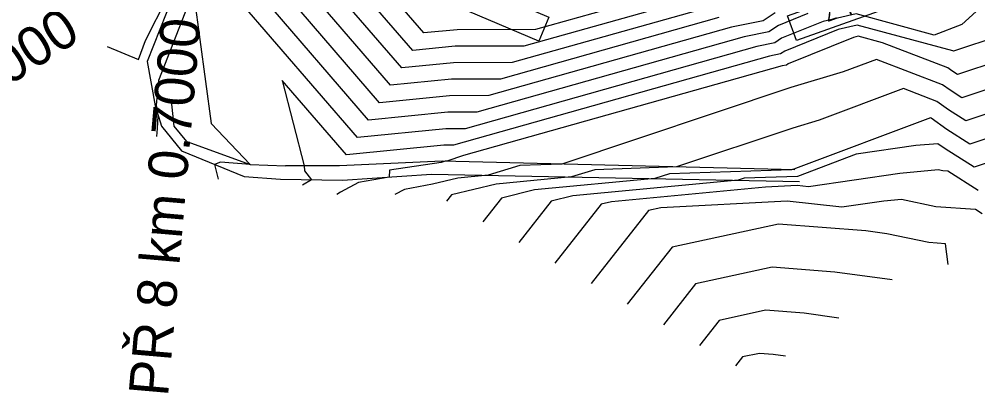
# Model space of a CAD drawing. Extents: x -549394 to -546608, y -1037055 to -1033629.
# Drawn here: x -548286 to -548066.1, y -1035761.5 to -1035675.8 of the extents above; entities that cross this region are included whole.
import ezdxf

# ---------------------------------------------------------------- set-up
doc = ezdxf.new("R2010")
doc.units = 0
for name, color, linetype in [('hlavni_vrst', 7, 'Continuous'), ('hrana_L', 7, 'Continuous'), ('norm_vrst', 7, 'Continuous'), ('x_popis_oblouky_C11', 7, 'Continuous'), ('x_popis_pricne_rezy_C11', 7, 'Continuous')]:
    doc.layers.add(name, color=color, linetype=linetype)

msp = doc.modelspace()

# ---------------------------------------------------------------- linework, layer by layer
at = {"layer": 'hlavni_vrst'}
for p, q in [((-548200.81, -1035690.94), (-548225.2, -1035662.65)), ((-548125.54, -1035675.43), (-548175.62, -1035689.53)), ((-548094.62, -1035679.95), (-548109.63, -1035686.05)), ((-548093.51, -1035679.7), (-548094.62, -1035679.95)), ((-548087.95, -1035681.2), (-548093.51, -1035679.7)), ((-548072.95, -1035686.97), (-548087.95, -1035681.2)), ((-548056.05, -1035683.58), (-548070.72, -1035688.47)), ((-548109.63, -1035686.05), (-548110, -1035686.3)), ((-548110.96, -1035686.49), (-548184.07, -1035707.08)), ((-548110, -1035686.3), (-548110.96, -1035686.49)), ((-548072.05, -1035687.62), (-548072.95, -1035686.97)), ((-548070.72, -1035688.47), (-548072.05, -1035687.62)), ((-548186.84, -1035689.56), (-548200.81, -1035690.94)), ((-548175.62, -1035689.53), (-548186.84, -1035689.56)), ((-548184.07, -1035707.08), (-548187.93, -1035708.37)), ((-548189.25, -1035708.68), (-548201.07, -1035710.46)), ((-548188.29, -1035708.38), (-548189.25, -1035708.68)), ((-548187.93, -1035708.37), (-548188.29, -1035708.38)), ((-548201.16, -1035712.01), (-548208.15, -1035713.27)), ((-548201.07, -1035710.46), (-548201.16, -1035712.01)), ((-548083.98, -1035711.17), (-548104.96, -1035714.23)), ((-548075.16, -1035710.39), (-548083.98, -1035711.17)), ((-548074.14, -1035710.6), (-548075.16, -1035710.39)), ((-548072.95, -1035710.68), (-548074.14, -1035710.6)), ((-548066.01, -1035715.11), (-548072.95, -1035710.68)), ((-548208.15, -1035713.27), (-548212.35, -1035715.5)), ((-548114.78, -1035714.32), (-548150.16, -1035717.69)), ((-548107.55, -1035713.94), (-548114.78, -1035714.32)), ((-548104.96, -1035714.23), (-548107.55, -1035713.94)), ((-548212.35, -1035715.5), (-548213.19, -1035716.03)), ((-548152.54, -1035718.27), (-548163.11, -1035731.75)), ((-548150.16, -1035717.69), (-548152.54, -1035718.27)), ((-548120.05, -1035753.31), (-548121.67, -1035755.37)), ((-548116.21, -1035752.48), (-548120.05, -1035753.31)), ((-548113.06, -1035752.73), (-548116.21, -1035752.48)), ((-548110.19, -1035753.12), (-548113.06, -1035752.73))]:
    msp.add_line(p, q, dxfattribs=at)
at = {"layer": 'hrana_L'}
for p, q in [((-548246.73, -1035660.38), (-548256.67, -1035685.46)), ((-548256.67, -1035685.46), (-548254.85, -1035695.64)), ((-548250.51, -1035700.32), (-548251.12, -1035694.53)), ((-548254.85, -1035695.64), (-548253.39, -1035700.3)), ((-548253.39, -1035700.3), (-548248.78, -1035706.03)), ((-548247.58, -1035703.85), (-548250.51, -1035700.32)), ((-548247.58, -1035703.85), (-548233.05, -1035709.12)), ((-548248.78, -1035706.03), (-548234.44, -1035711.9)), ((-548233.05, -1035709.12), (-548224.96, -1035709.46)), ((-548212.53, -1035709.4), (-548224.96, -1035709.46)), ((-548188.98, -1035708.34), (-548212.53, -1035709.4)), ((-548108.04, -1035710.38), (-548188.98, -1035708.34)), ((-548234.44, -1035711.9), (-548226.09, -1035712.52)), ((-548226.09, -1035712.52), (-548211.82, -1035712.72)), ((-548211.82, -1035712.72), (-548191.42, -1035711.36)), ((-548191.42, -1035711.36), (-548106.96, -1035713))]:
    msp.add_line(p, q, dxfattribs=at)
at = {"layer": 'norm_vrst'}
for p, q in [((-548257.09, -1035680.68), (-548246.91, -1035660.56)), ((-548208.42, -1035702.93), (-548243.86, -1035661.84)), ((-548205.88, -1035698.93), (-548237.64, -1035662.11)), ((-548203.34, -1035694.94), (-548231.42, -1035662.38)), ((-548198.27, -1035686.94), (-548218.99, -1035662.92)), ((-548195.73, -1035682.95), (-548212.77, -1035663.2)), ((-548193.19, -1035678.95), (-548206.55, -1035663.47)), ((-548254.02, -1035689.8), (-548246.08, -1035669.47)), ((-548246.08, -1035669.47), (-548241.98, -1035699.75)), ((-548134.28, -1035668.79), (-548167.54, -1035678.16)), ((-548131.37, -1035671), (-548170.23, -1035681.95)), ((-548063.08, -1035670.88), (-548069.73, -1035677)), ((-548128.45, -1035673.22), (-548172.93, -1035685.74)), ((-548112.56, -1035674.3), (-548115.36, -1035676.17)), ((-548105.08, -1035674.5), (-548111.82, -1035677.24)), ((-548093.96, -1035674.58), (-548101.59, -1035676.31)), ((-548076.09, -1035679.42), (-548093.96, -1035674.58)), ((-548115.36, -1035676.17), (-548122.62, -1035677.64)), ((-548111.82, -1035677.24), (-548114.02, -1035678.7)), ((-548101.59, -1035676.31), (-548111.09, -1035680.17)), ((-548093.73, -1035677.14), (-548098.1, -1035678.13)), ((-548071.83, -1035683.07), (-548093.73, -1035677.14)), ((-548069.73, -1035677), (-548076.09, -1035679.42)), ((-548185.55, -1035678.2), (-548193.19, -1035678.95)), ((-548167.54, -1035678.16), (-548185.55, -1035678.2)), ((-548122.62, -1035677.64), (-548178.31, -1035693.32)), ((-548114.02, -1035678.7), (-548119.7, -1035679.85)), ((-548098.1, -1035678.13), (-548110.36, -1035683.11)), ((-548054.66, -1035677.48), (-548071.66, -1035683.14)), ((-548258.63, -1035685.04), (-548257.09, -1035680.68)), ((-548119.7, -1035679.85), (-548181.01, -1035697.12)), ((-548112.68, -1035681.23), (-548116.79, -1035682.07)), ((-548111.09, -1035680.17), (-548112.68, -1035681.23)), ((-548265.87, -1035682.08), (-548258.63, -1035685.04)), ((-548185.98, -1035681.98), (-548195.73, -1035682.95)), ((-548170.23, -1035681.95), (-548185.98, -1035681.98)), ((-548116.79, -1035682.07), (-548183.7, -1035700.91)), ((-548111.34, -1035683.76), (-548113.87, -1035684.28)), ((-548110.36, -1035683.11), (-548111.34, -1035683.76)), ((-548071.68, -1035683.13), (-548071.83, -1035683.07)), ((-548071.67, -1035683.13), (-548071.68, -1035683.13)), ((-548071.66, -1035683.14), (-548071.67, -1035683.13)), ((-548186.41, -1035685.77), (-548198.27, -1035686.94)), ((-548172.93, -1035685.74), (-548186.41, -1035685.77)), ((-548113.87, -1035684.28), (-548186.39, -1035704.7)), ((-548089.33, -1035685), (-548097.01, -1035687.88)), ((-548074.22, -1035690.81), (-548089.33, -1035685)), ((-548097.01, -1035687.88), (-548109, -1035691.47)), ((-548254.56, -1035695.55), (-548254.02, -1035689.8)), ((-548210.96, -1035706.92), (-548225.67, -1035689.86)), ((-548225.67, -1035689.86), (-548220.64, -1035709.44)), ((-548057.44, -1035689.69), (-548069.78, -1035693.8)), ((-548109, -1035691.47), (-548161.56, -1035709.03)), ((-548083.12, -1035691.71), (-548102.45, -1035698.97)), ((-548075.49, -1035694.64), (-548083.12, -1035691.71)), ((-548072.43, -1035692.1), (-548074.22, -1035690.81)), ((-548069.78, -1035693.8), (-548072.43, -1035692.1)), ((-548187.27, -1035693.34), (-548203.34, -1035694.94)), ((-548178.31, -1035693.32), (-548187.27, -1035693.34)), ((-548072.82, -1035696.59), (-548075.49, -1035694.64)), ((-548254.12, -1035697.97), (-548254.56, -1035695.55)), ((-548181.01, -1035697.12), (-548187.7, -1035697.13)), ((-548068.83, -1035699.13), (-548072.82, -1035696.59)), ((-548058.83, -1035695.79), (-548068.83, -1035699.13)), ((-548254.3, -1035700.9), (-548254.12, -1035697.97)), ((-548187.7, -1035697.13), (-548205.88, -1035698.93)), ((-548102.45, -1035698.97), (-548108.53, -1035700.79)), ((-548076.9, -1035698.43), (-548107.88, -1035710.05)), ((-548076.75, -1035698.48), (-548076.9, -1035698.43)), ((-548073.2, -1035701.07), (-548076.75, -1035698.48)), ((-548254.47, -1035702.69), (-548254.3, -1035700.9)), ((-548241.98, -1035699.75), (-548233.05, -1035709.12)), ((-548188.13, -1035700.92), (-548208.42, -1035702.93)), ((-548183.7, -1035700.91), (-548188.13, -1035700.92)), ((-548108.53, -1035700.79), (-548135.2, -1035709.7)), ((-548067.89, -1035704.45), (-548073.2, -1035701.07)), ((-548060.22, -1035701.9), (-548067.89, -1035704.45)), ((-548188.57, -1035704.7), (-548210.96, -1035706.92)), ((-548186.39, -1035704.7), (-548188.57, -1035704.7)), ((-548080.34, -1035704.8), (-548093.98, -1035706.79)), ((-548075.24, -1035704.35), (-548080.34, -1035704.8)), ((-548073.58, -1035705.56), (-548075.24, -1035704.35)), ((-548066.95, -1035709.78), (-548073.58, -1035705.56)), ((-548093.98, -1035706.79), (-548107.43, -1035711.87)), ((-548061.61, -1035708), (-548066.95, -1035709.78)), ((-548239.87, -1035708.58), (-548241.25, -1035709.11)), ((-548241.25, -1035709.11), (-548240.38, -1035712.53)), ((-548233.05, -1035709.12), (-548239.87, -1035708.58)), ((-548233.05, -1035709.12), (-548233.05, -1035709.12)), ((-548233.05, -1035709.12), (-548233.05, -1035709.12)), ((-548233.05, -1035709.12), (-548233.05, -1035709.12)), ((-548220.64, -1035709.44), (-548220.54, -1035710.56)), ((-548171.13, -1035709.35), (-548178.43, -1035711.61)), ((-548161.56, -1035709.03), (-548171.13, -1035709.35)), ((-548135.2, -1035709.7), (-548153.98, -1035710.33)), ((-548108.05, -1035710.1), (-548108.83, -1035710.36)), ((-548107.88, -1035710.05), (-548108.05, -1035710.1)), ((-548220.54, -1035710.56), (-548218.96, -1035712.62)), ((-548185.43, -1035712.28), (-548191.18, -1035713.68)), ((-548178.43, -1035711.61), (-548185.43, -1035712.28)), ((-548159.32, -1035711.98), (-548176.61, -1035713.63)), ((-548140.21, -1035712.35), (-548167.79, -1035714.98)), ((-548153.98, -1035710.33), (-548159.32, -1035711.98)), ((-548136.82, -1035711.3), (-548140.21, -1035712.35)), ((-548108.83, -1035710.36), (-548136.82, -1035711.3)), ((-548119.66, -1035712.28), (-548121.1, -1035712.73)), ((-548107.43, -1035711.87), (-548119.66, -1035712.28)), ((-548218.96, -1035712.62), (-548221.01, -1035713.9)), ((-548191.18, -1035713.68), (-548197.66, -1035714.86)), ((-548176.61, -1035713.63), (-548186.83, -1035716.13)), ((-548121.1, -1035712.73), (-548158.98, -1035716.34)), ((-548197.66, -1035714.86), (-548199.84, -1035716.01)), ((-548186.83, -1035716.13), (-548187.97, -1035717.57)), ((-548175.4, -1035716.84), (-548179.68, -1035722.3)), ((-548167.79, -1035714.98), (-548175.4, -1035716.84)), ((-548158.98, -1035716.34), (-548163.97, -1035717.56)), ((-548163.97, -1035717.56), (-548171.39, -1035727.02)), ((-548138.81, -1035719.06), (-548141.65, -1035719.68)), ((-548109.8, -1035717.55), (-548138.81, -1035719.06)), ((-548097.26, -1035718.94), (-548109.8, -1035717.55)), ((-548087.62, -1035717.54), (-548097.26, -1035718.94)), ((-548083.57, -1035717.18), (-548087.62, -1035717.54)), ((-548075.74, -1035718.83), (-548083.57, -1035717.18)), ((-548066.62, -1035719.44), (-548075.74, -1035718.83)), ((-548141.65, -1035719.68), (-548154.82, -1035736.47)), ((-548065.06, -1035720.44), (-548066.62, -1035719.44)), ((-548111.85, -1035722.8), (-548136.25, -1035728.09)), ((-548091.77, -1035724.37), (-548111.85, -1035722.8)), ((-548086.95, -1035725.03), (-548091.77, -1035724.37)), ((-548077.34, -1035727.05), (-548086.95, -1035725.03)), ((-548073.5, -1035727.31), (-548077.34, -1035727.05)), ((-548072.91, -1035732.08), (-548073.5, -1035727.31)), ((-548136.25, -1035728.09), (-548146.53, -1035741.2)), ((-548113.3, -1035732.69), (-548130.85, -1035736.49)), ((-548098.87, -1035733.82), (-548113.3, -1035732.69)), ((-548085.74, -1035735.61), (-548098.87, -1035733.82)), ((-548130.85, -1035736.49), (-548138.24, -1035745.92)), ((-548114.76, -1035742.59), (-548125.45, -1035744.9)), ((-548105.96, -1035743.27), (-548114.76, -1035742.59)), ((-548097.96, -1035744.37), (-548105.96, -1035743.27)), ((-548125.45, -1035744.9), (-548129.96, -1035750.65))]:
    msp.add_line(p, q, dxfattribs=at)
at = {"layer": 'x_popis_oblouky_C11'}
for points in [[(-548166.84, -1035680.84), (-548194.42, -1035669.03), (-548192.06, -1035663.52), (-548164.48, -1035675.33)], [(-548079.46, -1035670.55), (-548107.7, -1035680.66), (-548109.73, -1035675.01), (-548081.48, -1035664.9)]]:
    msp.add_lwpolyline(points, close=True, dxfattribs=at)

# ---------------------------------------------------------------- texts
msp.add_text('Obl. 7', height=3.5, rotation=199.7205, dxfattribs=at).set_placement((-548090.02, -1035668.96))
at = {"layer": 'x_popis_pricne_rezy_C11'}
for s, rotation, p in [('PŘ 7 km 0.6000', 32.8121, (-548344.6, -1035727.33)), ('PŘ 8 km 0.7000', 85.0457, (-548251.91, -1035762.53))]:
    msp.add_text(s, height=9.0627, rotation=rotation, dxfattribs=at).set_placement(p)

doc.saveas('drawing.dxf')
